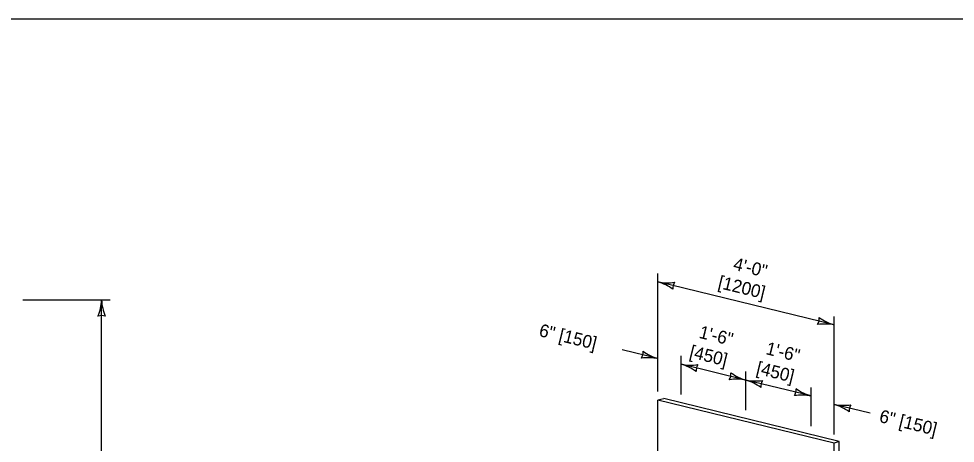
# Model space of a CAD drawing. Extents: x 49991.4 to 50021, y 49987.6 to 50011.4.
# Drawn here: x 50005.136 to 50009.529, y 49997.008 to 49998.999 of the extents above; entities that cross this region are included whole.
import ezdxf

# ---------------------------------------------------------------- set-up
doc = ezdxf.new("R2010")
doc.units = 0
for name, color, linetype in [('Level 1', 7, 'Continuous'), ('Level 2', 7, 'Continuous'), ('Level 3', 7, 'Continuous')]:
    doc.layers.add(name, color=color, linetype=linetype)

msp = doc.modelspace()

# ---------------------------------------------------------------- linework, layer by layer
at = {"layer": 'Level 1'}
for p, q in [((50008.1343, 49996.8632), (50008.1344, 49997.211)), ((50008.1615, 49997.2172), (50008.1344, 49997.211)), ((50008.9613, 49997.0091), (50008.1344, 49997.211)), ((50008.9838, 49997.0166), (50008.1615, 49997.2173)), ((50008.9838, 49997.0166), (50008.9613, 49997.0091)), ((50008.9613, 49994.8002), (50008.9613, 49997.0091)), ((50008.9838, 49994.8053), (50008.9838, 49997.0166))]:
    msp.add_line(p, q, dxfattribs=at)
msp.add_lwpolyline([(49999.3835, 49998.9992), (50016.7501, 49998.9992), (50016.7501, 49987.7988), (49999.3835, 49987.7988)], close=True, dxfattribs=at)
at = {"layer": 'Level 3'}
for p, q in [((50008.1344, 49997.251), (50008.1344, 49997.805)), ((50008.9613, 49997.5632), (50008.1344, 49997.765)), ((50005.1557, 49997.6802), (50005.5643, 49997.6802)), ((50005.5243, 49996.0925), (50005.5243, 49997.6802)), ((50008.9613, 49997.0491), (50008.9613, 49997.6032)), ((50008.1344, 49997.4051), (50007.966, 49997.4462)), ((50008.2433, 49997.2373), (50008.2433, 49997.4185)), ((50008.5469, 49997.3044), (50008.2433, 49997.3785)), ((50008.5469, 49997.1632), (50008.5469, 49997.3444)), ((50008.8525, 49997.2299), (50008.5469, 49997.3044)), ((50008.8525, 49997.0886), (50008.8525, 49997.2699)), ((50009.1297, 49997.1491), (50008.9613, 49997.1903))]:
    msp.add_line(p, q, dxfattribs=at)
for centre, radius, start, end in [((50008.0728, 49997.5514), 0.2223, 53.7399, 73.9234), ((50008.1784, 49997.9938), 0.233, 259.1112, 278.3611), ((50008.259, 49997.7346), 0.0548, 148.4227, 184.1451), ((50005.3022, 49997.6894), 0.2223, 337.456, 357.6395), ((50005.757, 49997.6917), 0.233, 182.8273, 202.0772), ((50005.5243, 49997.552), 0.0548, 72.1388, 107.8612), ((50008.8367, 49997.5936), 0.0548, 328.4227, 4.1451), ((50009.0229, 49997.7768), 0.2223, 233.7399, 253.9234), ((50008.9173, 49997.3344), 0.233, 79.1112, 98.3611), ((50008.0098, 49997.4355), 0.0548, 328.4272, 4.1495), ((50008.0904, 49997.1763), 0.233, 79.1157, 98.3655), ((50008.1959, 49997.6187), 0.2223, 233.7444, 253.9279), ((50008.1818, 49997.1648), 0.2223, 53.7456, 73.9291), ((50008.2873, 49997.6073), 0.233, 259.1169, 278.3667), ((50008.3679, 49997.3481), 0.0548, 148.4284, 184.1507), ((50008.4223, 49997.3348), 0.0548, 328.4284, 4.1507), ((50008.6084, 49997.518), 0.2223, 233.7456, 253.9291), ((50008.5029, 49997.0756), 0.233, 79.1169, 98.3667), ((50008.4854, 49997.0908), 0.2223, 53.7469, 73.9304), ((50008.5909, 49997.5332), 0.233, 259.1182, 278.368), ((50008.6715, 49997.274), 0.0548, 148.4297, 184.1521), ((50008.7279, 49997.2602), 0.0548, 328.4297, 4.1521), ((50008.8085, 49997.001), 0.233, 79.1182, 98.368), ((50008.914, 49997.4435), 0.2223, 233.7469, 253.9304), ((50008.8996, 49996.9767), 0.2223, 53.7154, 73.8989), ((50009.0054, 49997.4191), 0.233, 259.0867, 278.3365), ((50009.0858, 49997.1599), 0.0548, 148.3982, 184.1205)]:
    msp.add_arc(centre, radius, start, end, dxfattribs=at)

# ---------------------------------------------------------------- texts
at = {"layer": 'Level 2'}
for s, p in [('4\'-0"', (50008.4837, 49997.8227)), ('[1200]', (50008.4126, 49997.7371)), ('6" [150]', (50007.5727, 49997.5114)), ('1\'-6"', (50008.3234, 49997.503)), ('[450]', (50008.2786, 49997.4111)), ('1\'-6"', (50008.6367, 49997.4266)), ('[450]', (50008.5919, 49997.3346)), ('6" [150]', (50009.1687, 49997.1087))]:
    msp.add_text(s, height=0.06, rotation=346.28, dxfattribs=at).set_placement(p)

doc.saveas('drawing.dxf')
